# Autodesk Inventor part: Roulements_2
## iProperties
Created: 2002-06
Part Number: Roulements_2
Material: Par défaut
Document SubType Name: Modélisation
Designer: REVEST Pierre
Control State: 0
Master: False
Checked Out: False
Shininess: 20.0
Length Units: 11269
Angle Units: 11279
Time Units: 11290
Mass Units: 11283
Length Display Precision: 3
Angle Display Precision: 2
Density: 0.0
Volumn: 0.0
Area: 0.0
PropertySet Name: Model Information
Author: REVEST Pierre
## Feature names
1. Base1
